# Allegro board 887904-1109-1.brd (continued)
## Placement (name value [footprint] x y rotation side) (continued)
NOREF#991  -  []  441.63 509.49 90 top
NOREF#992  -  []  100.65 170.14 90 top
NOREF#993  -  []  96.65 195.83 0 top
NOREF#994  -  []  388.78 537.62 90 top
NOREF#995  -  []  471.24 516.22 0 top
NOREF#996  -  []  100.65 175.29 0 top
NOREF#997  -  []  431.7 114.13 90 top
R11  49.9-1-S4  [R0402]  121.79 233.76 180 bottom
R12  49.9-1-S4  [R0402]  119.59 233.76 180 bottom
R13  49.9-1-S4  [R0402]  117.39 233.76 180 bottom
R14  49.9-1-S4  [R0402]  115.19 233.76 180 bottom
R15  49.9-1-S4  [R0402]  112.98 233.76 180 bottom
R16  49.9-1-S4  [R0402]  110.78 233.76 180 bottom
R17  49.9-1-S4  [R0402]  108.58 233.76 180 bottom
R18  49.9-1-S4  [R0402]  106.37 233.76 180 bottom
R19  49.9-1-S4  [R0402]  104.17 233.76 180 bottom
R20  49.9-1-S4  [R0402]  101.97 233.76 180 bottom
R21  49.9-1-S4  [R0402]  99.76 233.76 180 bottom
R22  49.9-1-S4  [R0402]  97.56 233.76 180 bottom
R23  49.9-1-S4  [R0402]  95.36 233.76 180 bottom
R24  49.9-1-S4  [R0402]  93.15 233.76 180 bottom
R25  49.9-1-S4  [R0402]  90.95 233.76 180 bottom
R26  49.9-1-S4  [R0402]  88.75 233.76 180 bottom
R51  NC/1M-1-S4  [R0402]  103.37 200.03 180 bottom
R52  NC/1M-1-S4  [R0402]  100.83 200.03 180 bottom
R53  NC/100K-1-S4  [R0402]  98.29 200.03 180 bottom
R54  NC/100K-1-S4  [R0402]  95.75 200.03 180 bottom
R55  100K-1-S4  [R0402]  101.32 177.88 180 bottom
R69  NC/4.7K-1-S4  [R0402]  48.13 269.88 180 bottom
R70  NC/4.7K-1-S4  [R0402]  45.59 269.88 180 bottom
R71  NC/4.7K-1-S4  [R0402]  43.05 269.88 180 bottom
R72  4.7K-1-S4-WA  [R0402]  50.67 269.88 180 bottom
R73  NC/4.7K-1-S4  [R0402]  40.51 269.88 180 bottom
R74  NC/4.7K-1-S4  [R0402]  37.97 269.88 180 bottom
R147  1.1K-1-S4  [R0402]  51.73 245.19 180 bottom
R148  1.1K-1-S4  [R0402]  49.53 245.19 180 bottom
R161  0-5-S4  [R0402]  113.53 200.03 180 bottom
R162  0-5-S4  [R0402]  110.99 200.03 180 bottom
R163  4.7K-1-S4-WA  [R0402]  53.21 269.88 180 bottom
R184  50-0.1-S4-HF-VI  [R0402]  108.45 200.03 180 bottom
R185  50-0.1-S4-HF-VI  [R0402]  105.91 200.03 180 bottom
R200  0-5-S4  [R0402]  39.24 217.17 180 bottom
R201  0-5-S4  [R0402]  49.4 212.09 180 bottom
R202  0-5-S4  [R0402]  47.49 203.84 180 bottom
R203  0-5-S4  [R0402]  43.05 195.58 180 bottom
R204  0-5-S4  [R0402]  44.95 187.32 180 bottom
R205  0-5-S4  [R0402]  46.86 179.07 180 bottom
R206  0-5-S4  [R0402]  49.4 170.81 180 bottom
R207  0-5-S4  [R0402]  35.43 161.93 180 bottom
R208  0-5-S4  [R0402]  50.03 153.67 180 bottom
R209  0-5-S4  [R0402]  47.49 146.69 180 bottom
RB1  10K-1-S6  [R0603]  326.15 559.2 0 top
RB2  10K-1-S6  [R0603]  322.95 559.2 0 top
SB1  SHORT  [DEFAULT_SHORT_SMALL]  23.7 559.13 0 top
SB2  SHORT  [DEFAULT_SHORT_SMALL]  30.31 559.13 0 top
SB3  SHORT  [DEFAULT_SHORT_SMALL]  32.51 559.13 0 top
SB8  SHORT  [DEFAULT_SHORT_SMALL]  34.71 559.13 0 top
SB11  SHORT  [DEFAULT_SHORT_SMALL]  25.9 559.13 0 top
SB12  SHORT  [DEFAULT_SHORT_SMALL]  28.1 559.13 0 top
SCREW1  V93KMFHOLE  [PG_VG93K_F_FULLOUTLINE]  290.83 214.63 0 top
SH1  SHORT  [DEFAULT_SHORT_SMALL]  26.54 217.17 180 bottom
SH2  SHORT  [DEFAULT_SHORT_SMALL]  29.08 217.17 180 bottom
SH3  SHORT  [DEFAULT_SHORT_SMALL]  31.62 212.09 180 bottom
SH4  SHORT  [DEFAULT_SHORT_SMALL]  34.16 212.09 180 bottom
SH5  SHORT  [DEFAULT_SHORT_SMALL]  37.33 203.84 180 bottom
SH6  SHORT  [DEFAULT_SHORT_SMALL]  39.87 203.84 180 bottom
SH7  SHORT  [DEFAULT_SHORT_SMALL]  32.89 195.58 180 bottom
SH8  SHORT  [DEFAULT_SHORT_SMALL]  37.97 195.58 180 bottom
SH9  SHORT  [DEFAULT_SHORT_SMALL]  39.87 187.32 180 bottom
SH10  SHORT  [DEFAULT_SHORT_SMALL]  34.79 187.32 180 bottom
SH11  SHORT  [DEFAULT_SHORT_SMALL]  39.24 179.07 180 bottom
SH12  SHORT  [DEFAULT_SHORT_SMALL]  36.7 179.07 180 bottom
SH13  SHORT  [DEFAULT_SHORT_SMALL]  41.78 170.81 180 bottom
SH14  SHORT  [DEFAULT_SHORT_SMALL]  39.24 170.81 180 bottom
SH15  SHORT  [DEFAULT_SHORT_SMALL]  45.59 161.93 180 bottom
SH16  SHORT  [DEFAULT_SHORT_SMALL]  48.13 161.93 180 bottom
SH17  SHORT  [DEFAULT_SHORT_SMALL]  37.33 153.67 180 bottom
SH18  SHORT  [DEFAULT_SHORT_SMALL]  39.87 153.67 180 bottom
SH19  SHORT  [DEFAULT_SHORT_SMALL]  37.33 146.69 180 bottom
SH20  SHORT  [DEFAULT_SHORT_SMALL]  39.87 146.69 180 bottom
SH21  SHORT  [DEFAULT_SHORT_SMALL]  205.26 271.48 0 top
SH22  SHORT  [DEFAULT_SHORT_SMALL]  207.46 271.48 0 top
SH23  SHORT  [DEFAULT_SHORT_SMALL]  190.37 269.88 0 top
SH24  SHORT  [DEFAULT_SHORT_SMALL]  190.37 269.88 0 top
SH25  SHORT  [DEFAULT_SHORT_SMALL]  197.99 269.88 0 top
SH26  SHORT  [DEFAULT_SHORT_SMALL]  197.99 269.88 0 top
SITE1  CU/887904-WFBGA75-10X3.5X0.636  [SK_WFBGA75P_0P65MM_JG_887904]  230.7 214.63 270 top
SITE2  CU/887904-WFBGA75-10X3.5X0.636  [SK_WFBGA75P_0P65MM_JG_887904]  270.7 214.63 270 top
SITE3  CU/887904-WFBGA75-10X3.5X0.636  [SK_WFBGA75P_0P65MM_JG_887904]  310.7 214.63 270 top
SITE4  CU/887904-WFBGA75-10X3.5X0.636  [SK_WFBGA75P_0P65MM_JG_887904]  350.7 214.63 270 top
SKB1  SKB-HIMAX-2SITE-M5-140X140-HON  [SOCKETBASE_294X213_888003]  290.7 214.63 0 top
SW1  SW-SLIDE-1-D2.54-ECE  [SW_DIPX1_2P_H5MM]  116.71 175.26 180 bottom
TP_S1_V25  TP01  [TP_040_T]  205.61 269.24 0 top
TP_VDD09_CORE  TP01  [TP_040_T]  44.32 217.17 180 bottom
TP_VDD_EFUSE_POWER  TP01  [TP_040_T]  190.37 269.88 0 top
TP_VDD_EFUSE_POWER1  TP01  [TP_040_T]  197.99 269.88 0 top
TP_VDD_IOB_18_BOOST  TP01  [TP_040_T]  47.49 153.67 180 bottom
TP_VDD_IOB_18_POR  TP01  [TP_040_T]  31.62 147.32 180 bottom
TP_VDD_PLL_09  TP01  [TP_040_T]  37.97 161.93 180 bottom
TP_VDD_TX_09  TP01  [TP_040_T]  29.08 186.69 180 bottom
TP_VDD_TX_09_HDO  TP01  [TP_040_T]  30.35 203.84 180 bottom
TP_VDD_TXPST_09  TP01  [TP_040_T]  27.17 194.94 180 bottom
TP_VDDIO_18  TP01  [TP_040_T]  24 212.09 180 bottom
TP_VDDRX_09  TP01  [TP_040_T]  33.52 171.45 180 bottom
TP_VDDRX_AUX  TP01  [TP_040_T]  31.62 179.07 180 bottom
TPL1  TPL01  [TPL_040_014_TB]  615.92 559.38 0 top
TPL2  TPL01  [TPL_040_014_TB]  631.77 559.38 0 top
TPL3  TPL01  [TPL_040_014_TB]  156.78 265.43 90 top
TPL4  TPL01  [TPL_040_014_TB]  156.78 269.24 90 top
TPL5  TPL01  [TPL_040_014_TB]  156.78 273.05 90 top
TPL6  TPL01  [TPL_040_014_TB]  156.78 276.86 90 top
TPL7  TPL01  [TPL_040_014_TB]  156.78 280.67 90 top
TPL8  TPL01  [TPL_040_014_TB]  156.78 284.48 90 top
TPL9  TPL01  [TPL_040_014_TB]  156.78 288.29 90 top
TPL10  TPL01  [TPL_040_014_TB]  617.9 559.38 0 top
TPL11  TPL01  [TPL_040_014_TB]  619.88 559.38 0 top
TPL12  TPL01  [TPL_040_014_TB]  621.86 559.38 0 top
TPL13  TPL01  [TPL_040_014_TB]  623.85 559.38 0 top
TPL14  TPL01  [TPL_040_014_TB]  625.83 559.38 0 top
TPL15  TPL01  [TPL_040_014_TB]  627.81 559.38 0 top
TPL16  TPL01  [TPL_040_014_TB]  629.79 559.38 0 top
U5  SK-SO8-1.27-LOTES-150  [SK_SO8_150_1P27MM_LOTES]  25.02 262.29 180 bottom
UB1  AT24C04C-SSHM-SO8  [SO8_215X127MM]  511.27 524.59 0 top
UF1  MX25U4035FM1I-SOP8  [SOCKET_CODE]  35.43 269.88 180 bottom
UNK2C1  0.1U-16-X-S4-MU  [C0402]  312.64 559.05 0 top
UNK2C53  0.1U-16-X-S4-MU  [C0402]  310.43 559.05 0 top
UNK2C54  0.1U-16-X-S4-MU  [C0402]  308.23 559.05 0 top
UNK2C55  0.1U-16-X-S4-MU  [C0402]  306.03 559.05 0 top
UNK2C67  1U-10-X-S4-MU  [C0402]  266.37 559.05 0 top
UNK2C69  10U-25-X7R-SA  [C1206]  74.95 557.04 0 top
UNK2C70  10U-25-X7R-SA  [C1206]  70.35 557.04 0 top
UNK2C71  1U-10-X-S4-MU  [C0402]  264.17 559.05 0 top
UNK2C73  1U-10-X-S4-MU  [C0402]  261.96 559.05 0 top
UNK2C75  1U-10-X-S4-MU  [C0402]  259.76 559.05 0 top
UNK2C77  1U-10-X-S4-MU  [C0402]  257.56 559.05 0 top
UNK2C79  1U-10-X-S4-MU  [C0402]  255.35 559.05 0 top
UNK2C81  1U-10-X-S4-MU  [C0402]  253.15 559.05 0 top
UNK2C83  1U-10-X-S4-MU  [C0402]  250.95 559.05 0 top
UNK2C85  1U-10-X-S4-MU  [C0402]  248.74 559.05 0 top
UNK2C87  1U-10-X-S4-MU  [C0402]  246.54 559.05 0 top
UNK2C89  10U-25-X7R-SA  [C1206]  65.75 557.04 0 top
UNK2C90  10U-25-X7R-SA  [C1206]  61.14 557.04 0 top
UNK2C91  10U-25-X7R-SA  [C1206]  56.54 557.04 0 top
UNK2C92  10U-25-X7R-SA  [C1206]  51.94 557.04 0 top
UNK2C93  10U-25-X7R-SA  [C1206]  47.34 557.04 0 top
UNK2C94  10U-25-X7R-SA  [C1206]  627.61 538.78 0 top
UNK2C95  10U-25-X7R-SA  [C1206]  623.01 538.78 0 top
UNK2C96  10U-25-X7R-SA  [C1206]  618.4 538.78 0 top
UNK2CA1  NC/2.2U-10-X-S4-MU  [C0402]  437.28 538.08 0 top
UNK2CA2  NC/2.2U-10-X-S4-MU  [C0402]  432.87 538.08 0 top
UNK2CA3  NC/2.2U-10-X-S4-MU  [C0402]  430.67 538.08 0 top
UNK2CA4  NC/2.2U-10-X-S4-MU  [C0402]  123.42 559.05 0 top
UNK2CA5  NC/2.2U-10-X-S4-MU  [C0402]  121.22 559.05 0 top
UNK2CA6  NC/2.2U-10-X-S4-MU  [C0402]  119.01 559.05 0 top
UNK2CA7  NC/2.2U-10-X-S4-MU  [C0402]  137.04 556.34 0 top
UNK2CA8  NC/2.2U-10-X-S4-MU  [C0402]  133.44 556.34 0 top
UNK2CA9  NC/2.2U-10-X-S4-MU  [C0402]  131.23 556.34 0 top
UNK2CA10  NC/2.2U-10-X-S4-MU  [C0402]  435.08 538.08 0 top
UNK2CC1  0.47U-10-X6S-S2-TY  [C0201]  1.07 556.2 0 top
UNK2CC2  0.47U-10-X6S-S2-TY  [C0201]  630.61 537.94 0 top
UNK2CC3  0.47U-10-X6S-S2-TY  [C0201]  443.69 537.94 0 top
UNK2CC4  0.47U-10-X6S-S2-TY  [C0201]  354.5 537.94 0 top
UNK2CC5  0.47U-10-X6S-S2-TY  [C0201]  303.99 537.94 0 top
UNK2CC6  0.47U-10-X6S-S2-TY  [C0201]  289.96 537.94 0 top
UNK2CC7  0.47U-10-X6S-S2-TY  [C0201]  288.56 537.94 0 top
UNK2CC8  0.47U-10-X6S-S2-TY  [C0201]  284.35 537.94 0 top
UNK2CC9  0.47U-10-X6S-S2-TY  [C0201]  281.54 537.94 0 top
UNK2CC10  0.47U-10-X6S-S2-TY  [C0201]  -0.33 556.2 0 top
UNK2CC11  0.47U-10-X6S-S2-TY  [C0201]  -1.74 556.2 0 top
UNK2CC12  0.47U-10-X6S-S2-TY  [C0201]  -3.14 556.2 0 top
UNK2CC13  0.47U-10-X6S-S2-TY  [C0201]  634.82 537.94 0 top
UNK2CC14  0.47U-10-X6S-S2-TY  [C0201]  633.42 537.94 0 top
UNK2CC15  0.47U-10-X6S-S2-TY  [C0201]  632.01 537.94 0 top
UNK2CD1  0.1U-10-X7R-S2-MU  [C0201]  346.08 537.94 0 top
UNK2CD2  0.1U-10-X7R-S2-MU  [C0201]  398 537.94 0 top
UNK2CD3  0.1U-10-X7R-S2-MU  [C0201]  357.31 537.94 0 top
UNK2CD4  0.1U-10-X7R-S2-MU  [C0201]  358.71 537.94 0 top
UNK2CD5  0.1U-10-X7R-S2-MU  [C0201]  360.12 537.94 0 top
UNK2CD6  0.1U-10-X7R-S2-MU  [C0201]  361.52 537.94 0 top
UNK2CD7  0.1U-10-X7R-S2-MU  [C0201]  362.92 537.94 0 top
UNK2CD8  0.1U-10-X7R-S2-MU  [C0201]  364.32 537.94 0 top
UNK2CD9  0.1U-10-X7R-S2-MU  [C0201]  365.73 537.94 0 top
UNK2CD10  0.1U-10-X7R-S2-MU  [C0201]  347.49 537.94 0 top
UNK2CD11  0.1U-10-X7R-S2-MU  [C0201]  399.4 537.94 0 top
UNK2CD12  0.1U-10-X7R-S2-MU  [C0201]  350.29 537.94 0 top
UNK2CD13  0.1U-10-X7R-S2-MU  [C0201]  351.7 537.94 0 top
UNK2CD14  0.1U-10-X7R-S2-MU  [C0201]  353.1 537.94 0 top
UNK2CD15  0.1U-10-X7R-S2-MU  [C0201]  424.66 537.94 0 top
UNK2GND1  TP01  [TP_040_T]  20.92 582.23 0 top
UNK2K9  UA2-5NJ-A-V3  [RL_NECUA2_5V_V3]  408.95 524.93 0 top
UNK2K10  UA2-5NJ-A-V3  [RL_NECUA2_5V_V3]  475.57 524.93 0 top
UNK2K14  UA2-5NJ-A-V3  [RL_NECUA2_5V_V3]  464.47 524.93 0 top
UNK2K15  UA2-5NJ-A-V3  [RL_NECUA2_5V_V3]  453.36 524.93 0 top
UNK2K28  UA2-5NJ-A-V3  [RL_NECUA2_5V_V3]  442.26 524.93 0 top
UNK2K48  UA2-5NJ-A-V3  [RL_NECUA2_5V_V3]  431.16 524.93 0 top
UNK2K50  UA2-5NJ-A-V3  [RL_NECUA2_5V_V3]  420.06 524.93 0 top
UNK2K54  G6K-2F-RF-T-5V-SPECIAL  [RL_G6K2FRT_8P_5V_GR]  472.89 512.22 0 top
UNK2K55  EC2-5NJ-A  [RL_NECEC2_10P_5V]  512.55 510.07 0 top
UNK2K56  EC2-5NJ-A  [RL_NECEC2_10P_5V]  173.54 525.68 0 top
UNK2K57  EC2-5NJ-A  [RL_NECEC2_10P_5V]  158.33 525.68 0 top
UNK2K58  EC2-5NJ-A  [RL_NECEC2_10P_5V]  143.13 525.68 0 top
UNK2K59  EC2-5NJ-A  [RL_NECEC2_10P_5V]  127.93 525.68 0 top
UNK2K60  G6K-2F-RF-T-5V-SPECIAL  [RL_G6K2FRT_8P_5V_GR]  447.28 512.22 0 top
UNK2K61  G6K-2F-RF-T-5V-SPECIAL  [RL_G6K2FRT_8P_5V_GR]  370.46 512.22 0 top
UNK2K62  G6K-2F-RF-T-5V-SPECIAL  [RL_G6K2FRT_8P_5V_GR]  306.45 512.22 0 top
UNK2R11  49.9-1-S4  [R0402]  140.65 556.34 0 top
UNK2R12  49.9-1-S4  [R0402]  142.85 556.34 0 top
UNK2R13  49.9-1-S4  [R0402]  223.57 556.34 0 top
UNK2R14  49.9-1-S4  [R0402]  146.46 556.34 0 top
UNK2R15  49.9-1-S4  [R0402]  148.66 556.34 0 top
UNK2R16  49.9-1-S4  [R0402]  150.86 556.34 0 top
UNK2R17  49.9-1-S4  [R0402]  153.07 556.34 0 top
UNK2R18  49.9-1-S4  [R0402]  155.27 556.34 0 top
UNK2R19  49.9-1-S4  [R0402]  157.47 556.34 0 top
UNK2R20  49.9-1-S4  [R0402]  159.68 556.34 0 top
UNK2R21  49.9-1-S4  [R0402]  161.88 556.34 0 top
UNK2R22  49.9-1-S4  [R0402]  164.08 556.34 0 top
UNK2R23  49.9-1-S4  [R0402]  166.29 556.34 0 top
UNK2R24  49.9-1-S4  [R0402]  168.49 556.34 0 top
UNK2R25  49.9-1-S4  [R0402]  170.69 556.34 0 top
UNK2R26  49.9-1-S4  [R0402]  172.9 556.34 0 top
UNK2R51  NC/1M-1-S4  [R0402]  439.48 556.34 0 top
UNK2R52  NC/1M-1-S4  [R0402]  441.69 556.34 0 top
UNK2R53  NC/100K-1-S4  [R0402]  457.11 556.34 0 top
UNK2R54  NC/100K-1-S4  [R0402]  459.31 556.34 0 top
UNK2R55  100K-1-S4  [R0402]  474.73 556.34 0 top
UNK2R69  NC/4.7K-1-S4  [R0402]  483.55 556.34 0 top
UNK2R70  NC/4.7K-1-S4  [R0402]  485.75 556.34 0 top
UNK2R71  NC/4.7K-1-S4  [R0402]  487.95 556.34 0 top
UNK2R72  4.7K-1-S4-WA  [R0402]  406.44 556.34 0 top
UNK2R73  NC/4.7K-1-S4  [R0402]  490.16 556.34 0 top
UNK2R74  NC/4.7K-1-S4  [R0402]  492.36 556.34 0 top
UNK2R147  1.1K-1-S4  [R0402]  280.85 556.34 0 top
UNK2R148  1.1K-1-S4  [R0402]  283.06 556.34 0 top
UNK2R161  0-5-S4  [R0402]  298.48 556.34 0 top
UNK2R162  0-5-S4  [R0402]  300.68 556.34 0 top
UNK2R163  4.7K-1-S4-WA  [R0402]  404.23 556.34 0 top
UNK2R184  50-0.1-S4-HF-VI  [R0402]  421.86 556.34 0 top
UNK2R185  50-0.1-S4-HF-VI  [R0402]  424.06 556.34 0 top
UNK2R200  0-5-S4  [R0402]  302.89 556.34 0 top
UNK2R201  0-5-S4  [R0402]  305.09 556.34 0 top
UNK2R202  0-5-S4  [R0402]  307.29 556.34 0 top
UNK2R203  0-5-S4  [R0402]  309.49 556.34 0 top
UNK2R204  0-5-S4  [R0402]  311.7 556.34 0 top
UNK2R205  0-5-S4  [R0402]  313.9 556.34 0 top
UNK2R206  0-5-S4  [R0402]  316.1 556.34 0 top
UNK2R207  0-5-S4  [R0402]  318.31 556.34 0 top
UNK2R208  0-5-S4  [R0402]  320.51 556.34 0 top
UNK2R209  0-5-S4  [R0402]  322.71 556.34 0 top
UNK2SH1  SHORT  [DEFAULT_SHORT_SMALL]  527.61 556.43 0 top
UNK2SH2  SHORT  [DEFAULT_SHORT_SMALL]  551.85 556.43 0 top
UNK2SH3  SHORT  [DEFAULT_SHORT_SMALL]  556.25 556.43 0 top
UNK2SH4  SHORT  [DEFAULT_SHORT_SMALL]  558.46 556.43 0 top
UNK2SH5  SHORT  [DEFAULT_SHORT_SMALL]  560.66 556.43 0 top
UNK2SH6  SHORT  [DEFAULT_SHORT_SMALL]  562.86 556.43 0 top
UNK2SH7  SHORT  [DEFAULT_SHORT_SMALL]  565.07 556.43 0 top
UNK2SH8  SHORT  [DEFAULT_SHORT_SMALL]  567.27 556.43 0 top
UNK2SH9  SHORT  [DEFAULT_SHORT_SMALL]  569.47 556.43 0 top
UNK2SH10  SHORT  [DEFAULT_SHORT_SMALL]  529.81 556.43 0 top
UNK2SH11  SHORT  [DEFAULT_SHORT_SMALL]  532.02 556.43 0 top
UNK2SH12  SHORT  [DEFAULT_SHORT_SMALL]  534.22 556.43 0 top
UNK2SH13  SHORT  [DEFAULT_SHORT_SMALL]  536.42 556.43 0 top
UNK2SH14  SHORT  [DEFAULT_SHORT_SMALL]  538.63 556.43 0 top
UNK2SH15  SHORT  [DEFAULT_SHORT_SMALL]  540.83 556.43 0 top
UNK2SH16  SHORT  [DEFAULT_SHORT_SMALL]  543.03 556.43 0 top
UNK2SH17  SHORT  [DEFAULT_SHORT_SMALL]  545.24 556.43 0 top
UNK2SH18  SHORT  [DEFAULT_SHORT_SMALL]  547.44 556.43 0 top
UNK2SH19  SHORT  [DEFAULT_SHORT_SMALL]  549.64 556.43 0 top
UNK2SH20  SHORT  [DEFAULT_SHORT_SMALL]  554.05 556.43 0 top
UNK2SW1  SW-SLIDE-1-D2.54-ECE  [SW_DIPX1_2P_H5MM]  96.2 563.75 0 top
UNK2TP_VDD09_CORE  TP01  [TP_040_T]  18.94 582.23 0 top
UNK2TP_VDD_IOB_18_BOOST  TP01  [TP_040_T]  11.02 582.23 0 top
UNK2TP_VDD_IOB_18_POR  TP01  [TP_040_T]  613.94 559.38 0 top
UNK2TP_VDD_PLL_09  TP01  [TP_040_T]  611.96 559.38 0 top
UNK2TP_VDD_TX_09  TP01  [TP_040_T]  608 559.38 0 top
UNK2TP_VDD_TX_09_HDO  TP01  [TP_040_T]  606.01 559.38 0 top
UNK2TP_VDD_TXPST_09  TP01  [TP_040_T]  609.98 559.38 0 top
UNK2TP_VDDIO_18  TP01  [TP_040_T]  16.96 582.23 0 top
UNK2TP_VDDRX_09  TP01  [TP_040_T]  14.98 582.23 0 top
UNK2TP_VDDRX_AUX  TP01  [TP_040_T]  13 582.23 0 top
UNK2U5  SK-SO8-1.27-LOTES-150  [SK_SO8_150_1P27MM_LOTES]  547.66 514.02 0 top
UNK2UF1  MX25U4035FM1I-SOP8  [SOCKET_CODE]  334.66 558.9 0 top
UNK3C1  0.1U-16-X-S4-MU  [C0402]  303.82 559.05 0 top
UNK3C53  0.1U-16-X-S4-MU  [C0402]  301.62 559.05 0 top
UNK3C54  0.1U-16-X-S4-MU  [C0402]  299.42 559.05 0 top
UNK3C55  0.1U-16-X-S4-MU  [C0402]  297.21 559.05 0 top
UNK3C67  1U-10-X-S4-MU  [C0402]  244.34 559.05 0 top
UNK3C69  10U-25-X7R-SA  [C1206]  613.8 538.78 0 top
UNK3C70  10U-25-X7R-SA  [C1206]  609.2 538.78 0 top
UNK3C71  1U-10-X-S4-MU  [C0402]  242.13 559.05 0 top
UNK3C73  1U-10-X-S4-MU  [C0402]  239.93 559.05 0 top
UNK3C75  1U-10-X-S4-MU  [C0402]  237.73 559.05 0 top
UNK3C77  1U-10-X-S4-MU  [C0402]  235.52 559.05 0 top
UNK3C79  1U-10-X-S4-MU  [C0402]  233.32 559.05 0 top
UNK3C81  1U-10-X-S4-MU  [C0402]  231.12 559.05 0 top
UNK3C83  1U-10-X-S4-MU  [C0402]  228.91 559.05 0 top
UNK3C85  1U-10-X-S4-MU  [C0402]  226.71 559.05 0 top
UNK3C87  1U-10-X-S4-MU  [C0402]  224.51 559.05 0 top
UNK3C89  10U-25-X7R-SA  [C1206]  604.59 538.78 0 top
UNK3C90  10U-25-X7R-SA  [C1206]  599.99 538.78 0 top
UNK3C91  10U-25-X7R-SA  [C1206]  595.39 538.78 0 top
UNK3C92  10U-25-X7R-SA  [C1206]  590.78 538.78 0 top
UNK3C93  10U-25-X7R-SA  [C1206]  586.18 538.78 0 top
UNK3C94  10U-25-X7R-SA  [C1206]  581.58 538.78 0 top
UNK3C95  10U-25-X7R-SA  [C1206]  576.98 538.78 0 top
UNK3C96  10U-25-X7R-SA  [C1206]  572.37 538.78 0 top
UNK3CA1  NC/2.2U-10-X-S4-MU  [C0402]  129.03 556.34 0 top
UNK3CA2  NC/2.2U-10-X-S4-MU  [C0402]  124.62 556.34 0 top
UNK3CA3  NC/2.2U-10-X-S4-MU  [C0402]  122.42 556.34 0 top
UNK3CA4  NC/2.2U-10-X-S4-MU  [C0402]  120.22 556.34 0 top
UNK3CA5  NC/2.2U-10-X-S4-MU  [C0402]  118.01 556.34 0 top
UNK3CA6  NC/2.2U-10-X-S4-MU  [C0402]  115.81 556.34 0 top
UNK3CA7  NC/2.2U-10-X-S4-MU  [C0402]  113.61 556.34 0 top
UNK3CA8  NC/2.2U-10-X-S4-MU  [C0402]  111.4 556.34 0 top
UNK3CA9  NC/2.2U-10-X-S4-MU  [C0402]  109.2 556.34 0 top
UNK3CA10  NC/2.2U-10-X-S4-MU  [C0402]  126.83 556.34 0 top
UNK3CC1  0.47U-10-X6S-S2-TY  [C0201]  282.95 537.94 0 top
UNK3CC2  0.47U-10-X6S-S2-TY  [C0201]  305.39 537.94 0 top
UNK3CC3  0.47U-10-X6S-S2-TY  [C0201]  311.01 537.94 0 top
UNK3CC4  0.47U-10-X6S-S2-TY  [C0201]  295.57 537.94 0 top
UNK3CC5  0.47U-10-X6S-S2-TY  [C0201]  296.98 537.94 0 top
UNK3CC6  0.47U-10-X6S-S2-TY  [C0201]  298.38 537.94 0 top
UNK3CC7  0.47U-10-X6S-S2-TY  [C0201]  299.78 537.94 0 top
UNK3CC8  0.47U-10-X6S-S2-TY  [C0201]  315.22 537.94 0 top
UNK3CC9  0.47U-10-X6S-S2-TY  [C0201]  302.59 537.94 0 top
UNK3CC10  0.47U-10-X6S-S2-TY  [C0201]  292.77 537.94 0 top
UNK3CC11  0.47U-10-X6S-S2-TY  [C0201]  285.75 537.94 0 top
UNK3CC12  0.47U-10-X6S-S2-TY  [C0201]  287.15 537.94 0 top
UNK3CC13  0.47U-10-X6S-S2-TY  [C0201]  294.17 537.94 0 top
UNK3CC14  0.47U-10-X6S-S2-TY  [C0201]  301.19 537.94 0 top
UNK3CC15  0.47U-10-X6S-S2-TY  [C0201]  291.36 537.94 0 top
UNK3CD1  0.1U-10-X7R-S2-MU  [C0201]  367.13 537.94 0 top
UNK3CD2  0.1U-10-X7R-S2-MU  [C0201]  376.95 537.94 0 top
UNK3CD3  0.1U-10-X7R-S2-MU  [C0201]  378.36 537.94 0 top
UNK3CD4  0.1U-10-X7R-S2-MU  [C0201]  379.76 537.94 0 top
UNK3CD5  0.1U-10-X7R-S2-MU  [C0201]  381.16 537.94 0 top
UNK3CD6  0.1U-10-X7R-S2-MU  [C0201]  382.57 537.94 0 top
UNK3CD7  0.1U-10-X7R-S2-MU  [C0201]  445.09 537.94 0 top
UNK3CD8  0.1U-10-X7R-S2-MU  [C0201]  385.37 537.94 0 top
UNK3CD9  0.1U-10-X7R-S2-MU  [C0201]  386.77 537.94 0 top
UNK3CD10  0.1U-10-X7R-S2-MU  [C0201]  368.53 537.94 0 top
UNK3CD11  0.1U-10-X7R-S2-MU  [C0201]  369.94 537.94 0 top
UNK3CD12  0.1U-10-X7R-S2-MU  [C0201]  371.34 537.94 0 top
UNK3CD13  0.1U-10-X7R-S2-MU  [C0201]  372.74 537.94 0 top
UNK3CD14  0.1U-10-X7R-S2-MU  [C0201]  374.15 537.94 0 top
UNK3CD15  0.1U-10-X7R-S2-MU  [C0201]  375.55 537.94 0 top
UNK3GND1  TP01  [TP_040_T]  604.03 559.38 0 top
UNK3K9  UA2-5NJ-A-V3  [RL_NECUA2_5V_V3]  331.23 524.93 0 top
UNK3K10  UA2-5NJ-A-V3  [RL_NECUA2_5V_V3]  397.85 524.93 0 top
UNK3K14  UA2-5NJ-A-V3  [RL_NECUA2_5V_V3]  386.75 524.93 0 top
UNK3K15  UA2-5NJ-A-V3  [RL_NECUA2_5V_V3]  375.64 524.93 0 top
UNK3K28  UA2-5NJ-A-V3  [RL_NECUA2_5V_V3]  364.54 524.93 0 top
UNK3K48  UA2-5NJ-A-V3  [RL_NECUA2_5V_V3]  353.44 524.93 0 top
UNK3K50  UA2-5NJ-A-V3  [RL_NECUA2_5V_V3]  342.33 524.93 0 top
UNK3K54  G6K-2F-RF-T-5V-SPECIAL  [RL_G6K2FRT_8P_5V_GR]  319.25 512.22 0 top
UNK3K55  EC2-5NJ-A  [RL_NECEC2_10P_5V]  112.72 525.68 0 top
UNK3K56  EC2-5NJ-A  [RL_NECEC2_10P_5V]  97.52 525.68 0 top
UNK3K57  EC2-5NJ-A  [RL_NECEC2_10P_5V]  82.32 525.68 0 top
UNK3K58  EC2-5NJ-A  [RL_NECEC2_10P_5V]  67.11 525.68 0 top
UNK3K59  EC2-5NJ-A  [RL_NECEC2_10P_5V]  51.91 525.68 0 top
UNK3K60  G6K-2F-RF-T-5V-SPECIAL  [RL_G6K2FRT_8P_5V_GR]  332.05 512.22 0 top
UNK3K61  G6K-2F-RF-T-5V-SPECIAL  [RL_G6K2FRT_8P_5V_GR]  357.66 512.22 0 top
UNK3K62  G6K-2F-RF-T-5V-SPECIAL  [RL_G6K2FRT_8P_5V_GR]  344.85 512.22 0 top
UNK3R11  49.9-1-S4  [R0402]  175.1 556.34 0 top
UNK3R12  49.9-1-S4  [R0402]  177.3 556.34 0 top
UNK3R13  49.9-1-S4  [R0402]  179.51 556.34 0 top
UNK3R14  49.9-1-S4  [R0402]  181.71 556.34 0 top
UNK3R15  49.9-1-S4  [R0402]  183.91 556.34 0 top
UNK3R16  49.9-1-S4  [R0402]  186.12 556.34 0 top
UNK3R17  49.9-1-S4  [R0402]  188.32 556.34 0 top
UNK3R18  49.9-1-S4  [R0402]  190.52 556.34 0 top
UNK3R19  49.9-1-S4  [R0402]  192.73 556.34 0 top
UNK3R20  49.9-1-S4  [R0402]  194.93 556.34 0 top
UNK3R21  49.9-1-S4  [R0402]  197.13 556.34 0 top
UNK3R22  49.9-1-S4  [R0402]  314.84 559.05 0 top
UNK3R23  49.9-1-S4  [R0402]  317.04 559.05 0 top
UNK3R24  49.9-1-S4  [R0402]  203.74 556.34 0 top
UNK3R25  49.9-1-S4  [R0402]  205.94 556.34 0 top
UNK3R26  49.9-1-S4  [R0402]  208.15 556.34 0 top
UNK3R51  NC/1M-1-S4  [R0402]  443.89 556.34 0 top
UNK3R52  NC/1M-1-S4  [R0402]  446.09 556.34 0 top
UNK3R53  NC/100K-1-S4  [R0402]  461.52 556.34 0 top
UNK3R54  NC/100K-1-S4  [R0402]  463.72 556.34 0 top
UNK3R55  100K-1-S4  [R0402]  476.94 556.34 0 top
UNK3R69  NC/4.7K-1-S4  [R0402]  494.56 556.34 0 top
UNK3R70  NC/4.7K-1-S4  [R0402]  496.77 556.34 0 top
UNK3R71  NC/4.7K-1-S4  [R0402]  498.97 556.34 0 top
UNK3R72  4.7K-1-S4-WA  [R0402]  410.84 556.34 0 top
UNK3R73  NC/4.7K-1-S4  [R0402]  501.17 556.34 0 top
UNK3R74  NC/4.7K-1-S4  [R0402]  503.38 556.34 0 top
UNK3R147  1.1K-1-S4  [R0402]  285.26 556.34 0 top
UNK3R148  1.1K-1-S4  [R0402]  287.46 556.34 0 top
UNK3R161  0-5-S4  [R0402]  324.92 556.34 0 top
UNK3R162  0-5-S4  [R0402]  327.12 556.34 0 top
UNK3R163  4.7K-1-S4-WA  [R0402]  408.64 556.34 0 top
UNK3R184  50-0.1-S4-HF-VI  [R0402]  426.26 556.34 0 top
UNK3R185  50-0.1-S4-HF-VI  [R0402]  428.47 556.34 0 top
UNK3R200  0-5-S4  [R0402]  329.32 556.34 0 top
UNK3R201  0-5-S4  [R0402]  331.53 556.34 0 top
UNK3R202  0-5-S4  [R0402]  333.73 556.34 0 top
UNK3R203  0-5-S4  [R0402]  335.93 556.34 0 top
UNK3R204  0-5-S4  [R0402]  338.14 556.34 0 top
UNK3R205  0-5-S4  [R0402]  340.34 556.34 0 top
UNK3R206  0-5-S4  [R0402]  342.54 556.34 0 top
UNK3R207  0-5-S4  [R0402]  344.75 556.34 0 top
UNK3R208  0-5-S4  [R0402]  346.95 556.34 0 top
UNK3R209  0-5-S4  [R0402]  349.15 556.34 0 top
UNK3SH1  SHORT  [DEFAULT_SHORT_SMALL]  571.68 556.43 0 top
UNK3SH2  SHORT  [DEFAULT_SHORT_SMALL]  595.91 556.43 0 top
UNK3SH3  SHORT  [DEFAULT_SHORT_SMALL]  600.32 556.43 0 top
UNK3SH4  SHORT  [DEFAULT_SHORT_SMALL]  602.52 556.43 0 top
UNK3SH5  SHORT  [DEFAULT_SHORT_SMALL]  604.72 556.43 0 top
UNK3SH6  SHORT  [DEFAULT_SHORT_SMALL]  606.93 556.43 0 top
UNK3SH7  SHORT  [DEFAULT_SHORT_SMALL]  609.13 556.43 0 top
UNK3SH8  SHORT  [DEFAULT_SHORT_SMALL]  611.33 556.43 0 top
UNK3SH9  SHORT  [DEFAULT_SHORT_SMALL]  613.54 556.43 0 top
UNK3SH10  SHORT  [DEFAULT_SHORT_SMALL]  573.88 556.43 0 top
UNK3SH11  SHORT  [DEFAULT_SHORT_SMALL]  576.08 556.43 0 top
UNK3SH12  SHORT  [DEFAULT_SHORT_SMALL]  578.28 556.43 0 top
UNK3SH13  SHORT  [DEFAULT_SHORT_SMALL]  580.49 556.43 0 top
UNK3SH14  SHORT  [DEFAULT_SHORT_SMALL]  582.69 556.43 0 top
UNK3SH15  SHORT  [DEFAULT_SHORT_SMALL]  584.89 556.43 0 top
UNK3SH16  SHORT  [DEFAULT_SHORT_SMALL]  587.1 556.43 0 top
UNK3SH17  SHORT  [DEFAULT_SHORT_SMALL]  589.3 556.43 0 top
UNK3SH18  SHORT  [DEFAULT_SHORT_SMALL]  591.5 556.43 0 top
UNK3SH19  SHORT  [DEFAULT_SHORT_SMALL]  593.71 556.43 0 top
UNK3SH20  SHORT  [DEFAULT_SHORT_SMALL]  598.11 556.43 0 top
UNK3SW1  SW-SLIDE-1-D2.54-ECE  [SW_DIPX1_2P_H5MM]  102.4 563.75 0 top
UNK3TP_VDD09_CORE  TP01  [TP_040_T]  396.63 559.38 0 top
UNK3TP_VDD_IOB_18_BOOST  TP01  [TP_040_T]  388.7 559.38 0 top
UNK3TP_VDD_IOB_18_POR  TP01  [TP_040_T]  386.72 559.38 0 top
UNK3TP_VDD_PLL_09  TP01  [TP_040_T]  384.74 559.38 0 top
UNK3TP_VDD_TX_09  TP01  [TP_040_T]  462.01 559.38 0 top
UNK3TP_VDD_TX_09_HDO  TP01  [TP_040_T]  380.17 559.38 0 top
UNK3TP_VDD_TXPST_09  TP01  [TP_040_T]  597.43 559.38 0 top
UNK3TP_VDDIO_18  TP01  [TP_040_T]  394.65 559.38 0 top
UNK3TP_VDDRX_09  TP01  [TP_040_T]  392.67 559.38 0 top
UNK3TP_VDDRX_AUX  TP01  [TP_040_T]  390.69 559.38 0 top
UNK3U5  SK-SO8-1.27-LOTES-150  [SK_SO8_150_1P27MM_LOTES]  536.65 514.02 0 top
UNK3UF1  MX25U4035FM1I-SOP8  [SOCKET_CODE]  351.12 558.9 0 top
UNK4C1  0.1U-16-X-S4-MU  [C0402]  295.01 559.05 0 top
UNK4C53  0.1U-16-X-S4-MU  [C0402]  292.81 559.05 0 top
UNK4C54  0.1U-16-X-S4-MU  [C0402]  290.6 559.05 0 top
UNK4C55  0.1U-16-X-S4-MU  [C0402]  288.4 559.05 0 top
UNK4C67  1U-10-X-S4-MU  [C0402]  222.3 559.05 0 top
UNK4C69  10U-25-X7R-SA  [C1206]  567.77 538.78 0 top
UNK4C70  10U-25-X7R-SA  [C1206]  563.17 538.78 0 top
UNK4C71  1U-10-X-S4-MU  [C0402]  220.1 559.05 0 top
UNK4C73  1U-10-X-S4-MU  [C0402]  217.9 559.05 0 top
UNK4C75  1U-10-X-S4-MU  [C0402]  215.7 559.05 0 top
UNK4C77  1U-10-X-S4-MU  [C0402]  134.43 559.05 0 top
UNK4C79  1U-10-X-S4-MU  [C0402]  132.23 559.05 0 top
UNK4C81  1U-10-X-S4-MU  [C0402]  130.03 559.05 0 top
UNK4C83  1U-10-X-S4-MU  [C0402]  127.83 559.05 0 top
UNK4C85  1U-10-X-S4-MU  [C0402]  201.54 556.34 0 top
UNK4C87  1U-10-X-S4-MU  [C0402]  199.33 556.34 0 top
UNK4C89  10U-25-X7R-SA  [C1206]  558.56 538.78 0 top
UNK4C90  10U-25-X7R-SA  [C1206]  553.96 538.78 0 top
UNK4C91  10U-25-X7R-SA  [C1206]  549.36 538.78 0 top
UNK4C92  10U-25-X7R-SA  [C1206]  544.76 538.78 0 top
UNK4C93  10U-25-X7R-SA  [C1206]  540.15 538.78 0 top
UNK4C94  10U-25-X7R-SA  [C1206]  535.55 538.78 0 top
UNK4C95  10U-25-X7R-SA  [C1206]  530.95 538.78 0 top
UNK4C96  10U-25-X7R-SA  [C1206]  526.34 538.78 0 top
UNK4CA1  NC/2.2U-10-X-S4-MU  [C0402]  107 556.34 0 top
UNK4CA2  NC/2.2U-10-X-S4-MU  [C0402]  102.59 556.34 0 top
UNK4CA3  NC/2.2U-10-X-S4-MU  [C0402]  100.39 556.34 0 top
UNK4CA4  NC/2.2U-10-X-S4-MU  [C0402]  42.53 556.34 0 top
UNK4CA5  NC/2.2U-10-X-S4-MU  [C0402]  40.33 556.34 0 top
UNK4CA6  NC/2.2U-10-X-S4-MU  [C0402]  38.12 556.34 0 top
UNK4CA7  NC/2.2U-10-X-S4-MU  [C0402]  35.92 556.34 0 top
UNK4CA8  NC/2.2U-10-X-S4-MU  [C0402]  33.72 556.34 0 top
UNK4CA9  NC/2.2U-10-X-S4-MU  [C0402]  31.51 556.34 0 top
UNK4CA10  NC/2.2U-10-X-S4-MU  [C0402]  104.79 556.34 0 top
UNK4CC1  0.47U-10-X6S-S2-TY  [C0201]  327.84 537.94 0 top
UNK4CC2  0.47U-10-X6S-S2-TY  [C0201]  348.89 537.94 0 top
UNK4CC3  0.47U-10-X6S-S2-TY  [C0201]  334.86 537.94 0 top
UNK4CC4  0.47U-10-X6S-S2-TY  [C0201]  316.62 537.94 0 top
UNK4CC5  0.47U-10-X6S-S2-TY  [C0201]  318.02 537.94 0 top
UNK4CC6  0.47U-10-X6S-S2-TY  [C0201]  319.43 537.94 0 top
UNK4CC7  0.47U-10-X6S-S2-TY  [C0201]  320.83 537.94 0 top
UNK4CC8  0.47U-10-X6S-S2-TY  [C0201]  322.23 537.94 0 top
UNK4CC9  0.47U-10-X6S-S2-TY  [C0201]  323.64 537.94 0 top
UNK4CC10  0.47U-10-X6S-S2-TY  [C0201]  313.81 537.94 0 top
UNK4CC11  0.47U-10-X6S-S2-TY  [C0201]  306.8 537.94 0 top
UNK4CC12  0.47U-10-X6S-S2-TY  [C0201]  308.2 537.94 0 top
UNK4CC13  0.47U-10-X6S-S2-TY  [C0201]  309.6 537.94 0 top
UNK4CC14  0.47U-10-X6S-S2-TY  [C0201]  336.26 537.94 0 top
UNK4CC15  0.47U-10-X6S-S2-TY  [C0201]  312.41 537.94 0 top
UNK4CD1  0.1U-10-X7R-S2-MU  [C0201]  388.18 537.94 0 top
UNK4CD2  0.1U-10-X7R-S2-MU  [C0201]  135.24 556.2 0 top
UNK4CD3  0.1U-10-X7R-S2-MU  [C0201]  138.85 556.2 0 top
UNK4CD4  0.1U-10-X7R-S2-MU  [C0201]  400.81 537.94 0 top
UNK4CD5  0.1U-10-X7R-S2-MU  [C0201]  402.21 537.94 0 top
UNK4CD6  0.1U-10-X7R-S2-MU  [C0201]  403.61 537.94 0 top
UNK4CD7  0.1U-10-X7R-S2-MU  [C0201]  405.01 537.94 0 top
UNK4CD8  0.1U-10-X7R-S2-MU  [C0201]  406.42 537.94 0 top
UNK4CD9  0.1U-10-X7R-S2-MU  [C0201]  407.82 537.94 0 top
UNK4CD10  0.1U-10-X7R-S2-MU  [C0201]  389.58 537.94 0 top
UNK4CD11  0.1U-10-X7R-S2-MU  [C0201]  390.98 537.94 0 top
UNK4CD12  0.1U-10-X7R-S2-MU  [C0201]  392.39 537.94 0 top
UNK4CD13  0.1U-10-X7R-S2-MU  [C0201]  393.79 537.94 0 top
UNK4CD14  0.1U-10-X7R-S2-MU  [C0201]  395.19 537.94 0 top
UNK4CD15  0.1U-10-X7R-S2-MU  [C0201]  44.33 556.2 0 top
UNK4GND1  TP01  [TP_040_T]  426.7 559.38 0 top
UNK4K9  UA2-5NJ-A-V3  [RL_NECUA2_5V_V3]  253.51 524.93 0 top
UNK4K10  UA2-5NJ-A-V3  [RL_NECUA2_5V_V3]  320.13 524.93 0 top
UNK4K14  UA2-5NJ-A-V3  [RL_NECUA2_5V_V3]  309.02 524.93 0 top
UNK4K15  UA2-5NJ-A-V3  [RL_NECUA2_5V_V3]  297.92 524.93 0 top
UNK4K28  UA2-5NJ-A-V3  [RL_NECUA2_5V_V3]  286.82 524.93 0 top
UNK4K48  UA2-5NJ-A-V3  [RL_NECUA2_5V_V3]  275.71 524.93 0 top
UNK4K50  UA2-5NJ-A-V3  [RL_NECUA2_5V_V3]  264.61 524.93 0 top
UNK4K54  G6K-2F-RF-T-5V-SPECIAL  [RL_G6K2FRT_8P_5V_GR]  383.26 512.22 0 top
UNK4K55  EC2-5NJ-A  [RL_NECEC2_10P_5V]  36.71 525.68 0 top
UNK4K56  EC2-5NJ-A  [RL_NECEC2_10P_5V]  21.5 525.68 0 top
UNK4K57  EC2-5NJ-A  [RL_NECEC2_10P_5V]  6.3 525.68 0 top
UNK4K58  EC2-5NJ-A  [RL_NECEC2_10P_5V]  621.57 510.07 0 top
UNK4K59  EC2-5NJ-A  [RL_NECEC2_10P_5V]  606.37 510.07 0 top
UNK4K60  G6K-2F-RF-T-5V-SPECIAL  [RL_G6K2FRT_8P_5V_GR]  460.08 512.22 0 top
UNK4K61  G6K-2F-RF-T-5V-SPECIAL  [RL_G6K2FRT_8P_5V_GR]  485.69 512.22 0 top
UNK4K62  G6K-2F-RF-T-5V-SPECIAL  [RL_G6K2FRT_8P_5V_GR]  396.07 512.22 0 top
UNK4R11  49.9-1-S4  [R0402]  210.35 556.34 0 top
UNK4R12  49.9-1-S4  [R0402]  212.55 556.34 0 top
UNK4R13  49.9-1-S4  [R0402]  214.76 556.34 0 top
UNK4R14  49.9-1-S4  [R0402]  216.96 556.34 0 top
UNK4R15  49.9-1-S4  [R0402]  219.16 556.34 0 top
UNK4R16  49.9-1-S4  [R0402]  221.37 556.34 0 top
UNK4R17  49.9-1-S4  [R0402]  125.62 559.05 0 top
UNK4R18  49.9-1-S4  [R0402]  225.77 556.34 0 top
UNK4R19  49.9-1-S4  [R0402]  227.98 556.34 0 top
UNK4R20  49.9-1-S4  [R0402]  230.18 556.34 0 top
UNK4R21  49.9-1-S4  [R0402]  232.38 556.34 0 top
UNK4R22  49.9-1-S4  [R0402]  234.59 556.34 0 top
UNK4R23  49.9-1-S4  [R0402]  236.79 556.34 0 top
UNK4R24  49.9-1-S4  [R0402]  238.99 556.34 0 top
UNK4R25  49.9-1-S4  [R0402]  241.2 556.34 0 top
UNK4R26  49.9-1-S4  [R0402]  243.4 556.34 0 top
UNK4R51  NC/1M-1-S4  [R0402]  448.3 556.34 0 top
UNK4R52  NC/1M-1-S4  [R0402]  450.5 556.34 0 top
UNK4R53  NC/100K-1-S4  [R0402]  465.92 556.34 0 top
UNK4R54  NC/100K-1-S4  [R0402]  468.12 556.34 0 top
UNK4R55  100K-1-S4  [R0402]  479.14 556.34 0 top
UNK4R69  NC/4.7K-1-S4  [R0402]  505.58 556.34 0 top
UNK4R70  NC/4.7K-1-S4  [R0402]  507.78 556.34 0 top
UNK4R71  NC/4.7K-1-S4  [R0402]  509.99 556.34 0 top
UNK4R72  4.7K-1-S4-WA  [R0402]  415.25 556.34 0 top
UNK4R73  NC/4.7K-1-S4  [R0402]  512.19 556.34 0 top
UNK4R74  NC/4.7K-1-S4  [R0402]  514.39 556.34 0 top
UNK4R147  1.1K-1-S4  [R0402]  289.67 556.34 0 top
UNK4R148  1.1K-1-S4  [R0402]  291.87 556.34 0 top
UNK4R161  0-5-S4  [R0402]  351.36 556.34 0 top
UNK4R162  0-5-S4  [R0402]  353.56 556.34 0 top
UNK4R163  4.7K-1-S4-WA  [R0402]  413.04 556.34 0 top
UNK4R184  50-0.1-S4-HF-VI  [R0402]  430.67 556.34 0 top
UNK4R185  50-0.1-S4-HF-VI  [R0402]  432.87 556.34 0 top
UNK4R200  0-5-S4  [R0402]  355.76 556.34 0 top
UNK4R201  0-5-S4  [R0402]  357.96 556.34 0 top
UNK4R202  0-5-S4  [R0402]  360.17 556.34 0 top
UNK4R203  0-5-S4  [R0402]  362.37 556.34 0 top
UNK4R204  0-5-S4  [R0402]  364.57 556.34 0 top
UNK4R205  0-5-S4  [R0402]  366.78 556.34 0 top
UNK4R206  0-5-S4  [R0402]  368.98 556.34 0 top
UNK4R207  0-5-S4  [R0402]  371.18 556.34 0 top
UNK4R208  0-5-S4  [R0402]  373.39 556.34 0 top
UNK4R209  0-5-S4  [R0402]  375.59 556.34 0 top
UNK4SH1  SHORT  [DEFAULT_SHORT_SMALL]  615.74 556.43 0 top
UNK4SH2  SHORT  [DEFAULT_SHORT_SMALL]  3.87 559.13 0 top
UNK4SH3  SHORT  [DEFAULT_SHORT_SMALL]  8.28 559.13 0 top
UNK4SH4  SHORT  [DEFAULT_SHORT_SMALL]  10.48 559.13 0 top
UNK4SH5  SHORT  [DEFAULT_SHORT_SMALL]  12.68 559.13 0 top
UNK4SH6  SHORT  [DEFAULT_SHORT_SMALL]  14.88 559.13 0 top
UNK4SH7  SHORT  [DEFAULT_SHORT_SMALL]  17.09 559.13 0 top
UNK4SH8  SHORT  [DEFAULT_SHORT_SMALL]  19.29 559.13 0 top
UNK4SH9  SHORT  [DEFAULT_SHORT_SMALL]  21.49 559.13 0 top
UNK4SH10  SHORT  [DEFAULT_SHORT_SMALL]  617.94 556.43 0 top
UNK4SH11  SHORT  [DEFAULT_SHORT_SMALL]  620.15 556.43 0 top
UNK4SH12  SHORT  [DEFAULT_SHORT_SMALL]  622.35 556.43 0 top
UNK4SH13  SHORT  [DEFAULT_SHORT_SMALL]  624.55 556.43 0 top
UNK4SH14  SHORT  [DEFAULT_SHORT_SMALL]  626.75 556.43 0 top
UNK4SH15  SHORT  [DEFAULT_SHORT_SMALL]  628.96 556.43 0 top
UNK4SH16  SHORT  [DEFAULT_SHORT_SMALL]  631.16 556.43 0 top
UNK4SH17  SHORT  [DEFAULT_SHORT_SMALL]  -2.74 559.13 0 top
UNK4SH18  SHORT  [DEFAULT_SHORT_SMALL]  -0.54 559.13 0 top
UNK4SH19  SHORT  [DEFAULT_SHORT_SMALL]  1.67 559.13 0 top
UNK4SH20  SHORT  [DEFAULT_SHORT_SMALL]  6.07 559.13 0 top
UNK4SW1  SW-SLIDE-1-D2.54-ECE  [SW_DIPX1_2P_H5MM]  108.61 563.75 0 top
UNK4TP_VDD09_CORE  TP01  [TP_040_T]  376.21 559.38 0 top
UNK4TP_VDD_IOB_18_BOOST  TP01  [TP_040_T]  382.76 559.38 0 top
UNK4TP_VDD_IOB_18_POR  TP01  [TP_040_T]  366.3 559.38 0 top
UNK4TP_VDD_PLL_09  TP01  [TP_040_T]  364.32 559.38 0 top
UNK4TP_VDD_TX_09  TP01  [TP_040_T]  360.36 559.38 0 top
UNK4TP_VDD_TX_09_HDO  TP01  [TP_040_T]  358.38 559.38 0 top
UNK4TP_VDD_TXPST_09  TP01  [TP_040_T]  362.34 559.38 0 top
UNK4TP_VDDIO_18  TP01  [TP_040_T]  374.23 559.38 0 top
UNK4TP_VDDRX_09  TP01  [TP_040_T]  372.25 559.38 0 top
UNK4TP_VDDRX_AUX  TP01  [TP_040_T]  370.26 559.38 0 top
UNK4U5  SK-SO8-1.27-LOTES-150  [SK_SO8_150_1P27MM_LOTES]  525.65 514.02 0 top
UNK4UF1  MX25U4035FM1I-SOP8  [SOCKET_CODE]  381.45 558.9 0 top
UNK038HX-887904K4Q-A100  REF-CODE-PCB  [PCB_CODE]  23.42 581.75 0 top
UNK980HX-887904-KAG-  REF-CODE-PCB  [PCB_CODE]  22.81 581.75 0 top
UNK261103AA031  REF-CODE-SOCKET  [SOCKET_CODE]  22.2 581.75 0 top
UT_UP5V  TP03-D  [TP_060_040]  25.11 582.61 0 top
UTL1  V93K_UTL  [PG_VG93K_F_G3UTI1]  180.21 16.51 0 top
UTL2  V93K_UTL  [PG_VG93K_F_G1UTI2]  327.53 16.51 0 top
UTL3  V93K_UTL  [PG_VG93K_F_G2UTI3]  401.19 412.75 0 top
UTL4  V93K_UTL  [PG_VG93K_F_G8UTI4]  253.87 412.75 0 top
UTL5  V93K_UTL  [PG_VG93K_F_G4UTI5]  32.89 16.51 0 top
UTL6  V93K_UTL  [PG_VG93K_F_G5UTI6]  474.85 16.51 0 top
UTL7  V93K_UTL  [PG_VG93K_F_G6UTI7]  548.51 412.75 0 top
UTL8  V93K_UTL  [PG_VG93K_F_G7UTI8]  106.55 412.75 0 top
WFBGA-10X3.5X0.636-P0.65  REF-CODE-CHIP  [CHIP_CODE]  460.7 558.9 0 top

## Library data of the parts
BD29-BD44 = BD120-3A-S8: User Part Number: PNXXXXXXXXXX; Tolerance: TOL
C1 C53-C55 CB1 CB3 CB5 CB7 CB19 UNK2C1 UNK2C53-UNK2C55 UNK3C1 UNK3C53-UNK3C55 UNK4C1 UNK4C53-UNK4C55 = 0.1U-16-X-S4-MU: User Part Number: PNXXXXXXXXXX; Tolerance: TOL
C67 C71 C73 C75 C77 C79 C81 C83 C85 C87 UNK2C67 UNK2C71 UNK2C73 UNK2C75 UNK2C77 UNK2C79 UNK2C81 UNK2C83 UNK2C85 UNK2C87 UNK3C67 UNK3C71 UNK3C73 UNK3C75 UNK3C77 UNK3C79 UNK3C81 UNK3C83 UNK3C85 UNK3C87 UNK4C67 UNK4C71 UNK4C73 UNK4C75 UNK4C77 UNK4C79 UNK4C81 UNK4C83 UNK4C85 UNK4C87 = 1U-10-X-S4-MU: User Part Number: PNXXXXXXXXXX; Tolerance: TOL
C69 C70 C89-C96 CB2 CB4 CB6 CB8 CB10 CB12 CB14 CB16 UNK2C69 UNK2C70 UNK2C89-UNK2C96 UNK3C69 UNK3C70 UNK3C89-UNK3C96 UNK4C69 UNK4C70 UNK4C89-UNK4C96 = 10U-25-X7R-SA: User Part Number: PNXXXXXXXXXX; Tolerance: TOL
CA1-CA10 CA12-CA14 UNK2CA1-UNK2CA10 UNK3CA1-UNK3CA10 UNK4CA1-UNK4CA10 = 2.2U-10-X-S4-MU: User Part Number: PNXXXXXXXXXX; Tolerance: TOL
CB9 CB11 CB13 CB15 = 0.1U-25-X-S6: User Part Number: PNXXXXXXXXXX; Tolerance: TOL
CC1-CC15 UNK2CC1-UNK2CC15 UNK3CC1-UNK3CC15 UNK4CC1-UNK4CC15 = 0.47U-10-X6S-S2-TY: User Part Number: PNXXXXXXXXXX; Tolerance: TOL
CD1-CD15 UNK2CD1-UNK2CD15 UNK3CD1-UNK3CD15 UNK4CD1-UNK4CD15 = 0.1U-10-X7R-S2-MU: User Part Number: PNXXXXXXXXXX; Tolerance: TOL
CSDPS225 CSDPS229 CSDPS425 CSDPS429 = V93K_CSDPS_DPS32: User Part Number: PNXXXXXXXXXX; Tolerance: TOL
D101/D501 D102/D502 D103/D503 D105/D505 D106/D506 D107/D507 D117/D517 D118/D518 D119/D519 D121/D521 D122/D522 D123/D523 = V93K_PS1600_HD: User Part Number: PNXXXXXXXXXX; Tolerance: TOL
D104 D108-D116 D120 D124-D132 D201-D224 D231 D301 D302 D305 D306 D317 D318 D321 D322 D431 = V93K_CH: Tolerance: TOL; User Part Number: PNXXXXXXXXXX
DPS1-DPS5 DPS8 = V93K_DPS: Tolerance: TOL; User Part Number: PNXXXXXXXXXX
FD1-FD16 = FD_040_V2: Tolerance: TOL; User Part Number: PNXXXXXXXXXX
GND1 TP_S1_V25 TP_VDD09_CORE TP_VDD_EFUSE_POWER TP_VDD_EFUSE_POWER1 TP_VDD_IOB_18_BOOST TP_VDD_IOB_18_POR TP_VDD_PLL_09 TP_VDD_TX_09 TP_VDD_TX_09_HDO TP_VDD_TXPST_09 TP_VDDIO_18 TP_VDDRX_09 TP_VDDRX_AUX UNK2GND1 UNK2TP_VDD09_CORE UNK2TP_VDD_IOB_18_BOOST UNK2TP_VDD_IOB_18_POR UNK2TP_VDD_PLL_09 UNK2TP_VDD_TX_09 UNK2TP_VDD_TX_09_HDO UNK2TP_VDD_TXPST_09 UNK2TP_VDDIO_18 UNK2TP_VDDRX_09 UNK2TP_VDDRX_AUX UNK3GND1 UNK3TP_VDD09_CORE UNK3TP_VDD_IOB_18_BOOST UNK3TP_VDD_IOB_18_POR UNK3TP_VDD_PLL_09 UNK3TP_VDD_TX_09 UNK3TP_VDD_TX_09_HDO UNK3TP_VDD_TXPST_09 UNK3TP_VDDIO_18 UNK3TP_VDDRX_09 UNK3TP_VDDRX_AUX UNK4GND1 UNK4TP_VDD09_CORE UNK4TP_VDD_IOB_18_BOOST UNK4TP_VDD_IOB_18_POR UNK4TP_VDD_PLL_09 UNK4TP_VDD_TX_09 UNK4TP_VDD_TX_09_HDO UNK4TP_VDD_TXPST_09 UNK4TP_VDDIO_18 UNK4TP_VDDRX_09 UNK4TP_VDDRX_AUX = TP01: Tolerance: TOL; User Part Number: PNXXXXXXXXXX
HX8879-F04 WFBGA-10X3.5X0.636-P0.65 = REF-CODE-CHIP
K9 K10 K14 K15 K28 K48 K50 UNK2K9 UNK2K10 UNK2K14 UNK2K15 UNK2K28 UNK2K48 UNK2K50 UNK3K9 UNK3K10 UNK3K14 UNK3K15 UNK3K28 UNK3K48 UNK3K50 UNK4K9 UNK4K10 UNK4K14 UNK4K15 UNK4K28 UNK4K48 UNK4K50 = UA2-5NJ-A-V3: Tolerance: TOL; User Part Number: PNXXXXXXXXXX
K54 K60-K62 UNK2K54 UNK2K60-UNK2K62 UNK3K54 UNK3K60-UNK3K62 UNK4K54 UNK4K60-UNK4K62 = G6K-2F-RF-T-5V-SPECIAL: Tolerance: TOL; User Part Number: PNXXXXXXXXXX
K55-K59 UNK2K55-UNK2K59 UNK3K55-UNK3K59 UNK4K55-UNK4K59 = EC2-5NJ-A: Tolerance: TOL; User Part Number: PNXXXXXXXXXX
LDB1 = LDB-2-S8: User Part Number: PNXXXXXXXXXX; Tolerance: TOL
LOGO1 = LOGO_KT_KSMT
LOGO2 = LOGO_HX_Himax
LRB1 = 330-1-S6: User Part Number: PNXXXXXXXXXX; Tolerance: TOL
R11-R26 UNK2R11-UNK2R26 UNK3R11-UNK3R26 UNK4R11-UNK4R26 = 49.9-1-S4: User Part Number: PNXXXXXXXXXX; Tolerance: TOL
R51 R52 UNK2R51 UNK2R52 UNK3R51 UNK3R52 UNK4R51 UNK4R52 = 1M-1-S4: User Part Number: PNXXXXXXXXXX; Tolerance: TOL
R53-R55 UNK2R53-UNK2R55 UNK3R53-UNK3R55 UNK4R53-UNK4R55 = 100K-1-S4: User Part Number: PNXXXXXXXXXX; Tolerance: TOL
R69-R74 R163 UNK2R69-UNK2R74 UNK2R163 UNK3R69-UNK3R74 UNK3R163 UNK4R69-UNK4R74 UNK4R163 = 4.7K-1-S4-WA: User Part Number: PNXXXXXXXXXX; Tolerance: TOL
R147 R148 UNK2R147 UNK2R148 UNK3R147 UNK3R148 UNK4R147 UNK4R148 = 1.1K-1-S4: User Part Number: PNXXXXXXXXXX; Tolerance: TOL
R161 R162 R200-R209 UNK2R161 UNK2R162 UNK2R200-UNK2R209 UNK3R161 UNK3R162 UNK3R200-UNK3R209 UNK4R161 UNK4R162 UNK4R200-UNK4R209 = 0-5-S4: User Part Number: PNXXXXXXXXXX; Tolerance: TOL
R184 R185 UNK2R184 UNK2R185 UNK3R184 UNK3R185 UNK4R184 UNK4R185 = 50-0.1-S4-HF-VI: User Part Number: PNXXXXXXXXXX; Tolerance: TOL
RB1 RB2 = 10K-1-S6: User Part Number: PNXXXXXXXXXX; Tolerance: TOL
SB1-SB3 SB8 SB11 SB12 SH1-SH26 UNK2SH1-UNK2SH20 UNK3SH1-UNK3SH20 UNK4SH1-UNK4SH20 = SHORT: User Part Number: PNXXXXXXXXXX; Tolerance: TOL
SCREW1 = V93KMFHOLE: Tolerance: TOL; User Part Number: PNXXXXXXXXXX
SITE1-SITE4 = CU/887904-WFBGA75-10X3.5X0.636: Tolerance: TOL; User Part Number: PNXXXXXXXXXX
SKB1 = SKB-HIMAX-2SITE-M5-140X140-HON: Tolerance: TOL; User Part Number: PNXXXXXXXXXX
SW1 UNK2SW1 UNK3SW1 UNK4SW1 = SW-SLIDE-1-D2.54-ECE: Tolerance: TOL; User Part Number: PNXXXXXXXXXX
TPL1-TPL16 = TPL01: Tolerance: TOL; User Part Number: PNXXXXXXXXXX
U5 UNK2U5 UNK3U5 UNK4U5 = MX25V4006EM1I-13G-SO8: User Part Number: PNXXXXXXXXXX; Tolerance: TOL
UB1 = AT24C04C-SSHM-SO8: User Part Number: PNXXXXXXXXXX; Tolerance: TOL
UF1 UNK2UF1 UNK3UF1 UNK4UF1 = REF-CODE-FLASH
UNK038HX-887904K4Q-A100 UNK980HX-887904-KAG- = REF-CODE-PCB
UNK261103AA031 = REF-CODE-SOCKET
UT_UP5V = TP03-D: Tolerance: TOL; User Part Number: PNXXXXXXXXXX
UTL1-UTL8 = V93K_UTL: User Part Number: PNXXXXXXXXXX; Tolerance: TOL

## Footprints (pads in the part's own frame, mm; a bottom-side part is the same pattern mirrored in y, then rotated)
C0201
  rect 0.305x0.356 smd: 1(-0.3,0) 2(0.3,0)
C0402
  custom 0.15x0.15 smd: 1(-0.5,0) 2(0.5,0)
C0603
  rect 0.889x0.889 smd: 1(-0.85,0) 2(0.85,0)
C1206
  rect 1.321x1.829 smd: 1(-1.25,0) 2(1.25,0)
CHIP_CODE
  round 0.051 smd: 1(0,0)
DEFAULT_SHORT_SMALL
  custom 0.07x0.07 smd: 1(-0.5,0) 2(0.5,0)
FB0805
  rect 1.118x1.372 smd: 1(-0.965,0) 2(0.965,0)
FD_040_V2
  round 1.016 smd: 1(0,0)
LED_0805
  rect 1.118x1.372 smd: 1(0.95,0) 2(-0.95,0)
LOGO_HX_HIMAX
  round 0.051 smd: 1(0.831,1.487)
LOGO_KT_KSMT
  round 0.051 smd: 1(-0.711,-0.711)
PCB_CODE
  round 0.051 smd: 1(0,0)
PG_VG93K_F_FULLOUTLINE
  round 0.508 hole 3.2 unplated: (-287.604,198.12) (-287.604,102.006) (-287.604,0) (-287.604,-102.006) (-287.604,-198.12) (-220.98,157.48) (-220.98,-157.48) (-140.276,198.12) (-140.276,102.006) (-140.276,0) (-140.276,-102.006) (-140.276,-198.12) (-73.66,157.48) (-73.66,-157.48) (7.044,198.12) (7.044,102.006) (7.044,-102.006) (7.044,-198.12) (73.66,157.48) (73.66,-157.48) (140.304,198.12) (140.304,102.006) (140.304,0) (140.304,-102.006) (140.304,-198.12) (220.98,157.48) (220.98,-157.48) (287.604,198.12) (287.604,102.006) (287.604,0) (287.604,-102.006) (287.604,-198.12)
  round 0.508 hole 6 unplated: (-70,70) (-70,-70) (70,70) (70,-70)
PG_VG93K_F_G1D104
  round 1.778 hole 0.711: 01(-20.32,-1.27) 02(-17.78,1.27) 03(-15.24,-1.27) 04(-12.7,1.27) 05(-10.16,-1.27) 06(-7.62,1.27) 07(-5.08,-1.27) 08(-2.54,1.27) 09(0,-1.27) 10(2.54,1.27) 11(5.08,-1.27) 12(7.62,1.27) 13(10.16,-1.27) 14(12.7,1.27) 15(15.24,-1.27) 16(17.78,1.27) 17(20.32,-1.27)
  rect 1.778x1.778 hole 0.711: A1(-20.32,-3.81) A2(-17.78,-1.27) A3(-15.24,-3.81) A4(-12.7,-1.27) A5(-10.16,-3.81) A6(-7.62,-1.27) A7(-5.08,-3.81) A8(-2.54,-1.27) A9(0,-3.81) A10(2.54,-1.27) A11(5.08,-3.81) A12(7.62,-1.27) A13(10.16,-3.81) A14(12.7,-1.27) A15(15.24,-3.81) A16(17.78,-1.27) A17(20.32,-3.81) B1(-20.32,1.27) B2(-17.78,3.81) B3(-15.24,1.27) B4(-12.7,3.81) B5(-10.16,1.27) B6(-7.62,3.81) B7(-5.08,1.27) B8(-2.54,3.81) B9(0,1.27) B10(2.54,3.81) B11(5.08,1.27) B12(7.62,3.81) B13(10.16,1.27) B14(12.7,3.81) B15(15.24,1.27) B16(17.78,3.81) B17(20.32,1.27)
PG_VG93K_F_G1D108
  round 1.778 hole 0.711: 01(-20.32,-1.27) 02(-17.78,1.27) 03(-15.24,-1.27) 04(-12.7,1.27) 05(-10.16,-1.27) 06(-7.62,1.27) 07(-5.08,-1.27) 08(-2.54,1.27) 09(0,-1.27) 10(2.54,1.27) 11(5.08,-1.27) 12(7.62,1.27) 13(10.16,-1.27) 14(12.7,1.27) 15(15.24,-1.27) 16(17.78,1.27) 17(20.32,-1.27)
  rect 1.778x1.778 hole 0.711: A1(-20.32,-3.81) A2(-17.78,-1.27) A3(-15.24,-3.81) A4(-12.7,-1.27) A5(-10.16,-3.81) A6(-7.62,-1.27) A7(-5.08,-3.81) A8(-2.54,-1.27) A9(0,-3.81) A10(2.54,-1.27) A11(5.08,-3.81) A12(7.62,-1.27) A13(10.16,-3.81) A14(12.7,-1.27) A15(15.24,-3.81) A16(17.78,-1.27) A17(20.32,-3.81) B1(-20.32,1.27) B2(-17.78,3.81) B3(-15.24,1.27) B4(-12.7,3.81) B5(-10.16,1.27) B6(-7.62,3.81) B7(-5.08,1.27) B8(-2.54,3.81) B9(0,1.27) B10(2.54,3.81) B11(5.08,1.27) B12(7.62,3.81) B13(10.16,1.27) B14(12.7,3.81) B15(15.24,1.27) B16(17.78,3.81) B17(20.32,1.27)
PG_VG93K_F_G1D301
  round 1.778 hole 0.711: 01(-20.32,-1.27) 02(-17.78,1.27) 03(-15.24,-1.27) 04(-12.7,1.27) 05(-10.16,-1.27) 06(-7.62,1.27) 07(-5.08,-1.27) 08(-2.54,1.27) 09(0,-1.27) 10(2.54,1.27) 11(5.08,-1.27) 12(7.62,1.27) 13(10.16,-1.27) 14(12.7,1.27) 15(15.24,-1.27) 16(17.78,1.27) 17(20.32,-1.27)
  rect 1.778x1.778 hole 0.711: A1(-20.32,-3.81) A2(-17.78,-1.27) A3(-15.24,-3.81) A4(-12.7,-1.27) A5(-10.16,-3.81) A6(-7.62,-1.27) A7(-5.08,-3.81) A8(-2.54,-1.27) A9(0,-3.81) A10(2.54,-1.27) A11(5.08,-3.81) A12(7.62,-1.27) A13(10.16,-3.81) A14(12.7,-1.27) A15(15.24,-3.81) A16(17.78,-1.27) A17(20.32,-3.81) B1(-20.32,1.27) B2(-17.78,3.81) B3(-15.24,1.27) B4(-12.7,3.81) B5(-10.16,1.27) B6(-7.62,3.81) B7(-5.08,1.27) B8(-2.54,3.81) B9(0,1.27) B10(2.54,3.81) B11(5.08,1.27) B12(7.62,3.81) B13(10.16,1.27) B14(12.7,3.81) B15(15.24,1.27) B16(17.78,3.81) B17(20.32,1.27)
PG_VG93K_F_G1D302
  round 1.778 hole 0.711: 01(-20.32,-1.27) 02(-17.78,1.27) 03(-15.24,-1.27) 04(-12.7,1.27) 05(-10.16,-1.27) 06(-7.62,1.27) 07(-5.08,-1.27) 08(-2.54,1.27) 09(0,-1.27) 10(2.54,1.27) 11(5.08,-1.27) 12(7.62,1.27) 13(10.16,-1.27) 14(12.7,1.27) 15(15.24,-1.27) 16(17.78,1.27) 17(20.32,-1.27)
  rect 1.778x1.778 hole 0.711: A1(-20.32,-3.81) A2(-17.78,-1.27) A3(-15.24,-3.81) A4(-12.7,-1.27) A5(-10.16,-3.81) A6(-7.62,-1.27) A7(-5.08,-3.81) A8(-2.54,-1.27) A9(0,-3.81) A10(2.54,-1.27) A11(5.08,-3.81) A12(7.62,-1.27) A13(10.16,-3.81) A14(12.7,-1.27) A15(15.24,-3.81) A16(17.78,-1.27) A17(20.32,-3.81) B1(-20.32,1.27) B2(-17.78,3.81) B3(-15.24,1.27) B4(-12.7,3.81) B5(-10.16,1.27) B6(-7.62,3.81) B7(-5.08,1.27) B8(-2.54,3.81) B9(0,1.27) B10(2.54,3.81) B11(5.08,1.27) B12(7.62,3.81) B13(10.16,1.27) B14(12.7,3.81) B15(15.24,1.27) B16(17.78,3.81) B17(20.32,1.27)
PG_VG93K_F_G1D305
  round 1.778 hole 0.711: 01(-20.32,-1.27) 02(-17.78,1.27) 03(-15.24,-1.27) 04(-12.7,1.27) 05(-10.16,-1.27) 06(-7.62,1.27) 07(-5.08,-1.27) 08(-2.54,1.27) 09(0,-1.27) 10(2.54,1.27) 11(5.08,-1.27) 12(7.62,1.27) 13(10.16,-1.27) 14(12.7,1.27) 15(15.24,-1.27) 16(17.78,1.27) 17(20.32,-1.27)
  rect 1.778x1.778 hole 0.711: A1(-20.32,-3.81) A2(-17.78,-1.27) A3(-15.24,-3.81) A4(-12.7,-1.27) A5(-10.16,-3.81) A6(-7.62,-1.27) A7(-5.08,-3.81) A8(-2.54,-1.27) A9(0,-3.81) A10(2.54,-1.27) A11(5.08,-3.81) A12(7.62,-1.27) A13(10.16,-3.81) A14(12.7,-1.27) A15(15.24,-3.81) A16(17.78,-1.27) A17(20.32,-3.81) B1(-20.32,1.27) B2(-17.78,3.81) B3(-15.24,1.27) B4(-12.7,3.81) B5(-10.16,1.27) B6(-7.62,3.81) B7(-5.08,1.27) B8(-2.54,3.81) B9(0,1.27) B10(2.54,3.81) B11(5.08,1.27) B12(7.62,3.81) B13(10.16,1.27) B14(12.7,3.81) B15(15.24,1.27) B16(17.78,3.81) B17(20.32,1.27)
PG_VG93K_F_G1D306
  round 1.778 hole 0.711: 01(-20.32,-1.27) 02(-17.78,1.27) 03(-15.24,-1.27) 04(-12.7,1.27) 05(-10.16,-1.27) 06(-7.62,1.27) 07(-5.08,-1.27) 08(-2.54,1.27) 09(0,-1.27) 10(2.54,1.27) 11(5.08,-1.27) 12(7.62,1.27) 13(10.16,-1.27) 14(12.7,1.27) 15(15.24,-1.27) 16(17.78,1.27) 17(20.32,-1.27)
  rect 1.778x1.778 hole 0.711: A1(-20.32,-3.81) A2(-17.78,-1.27) A3(-15.24,-3.81) A4(-12.7,-1.27) A5(-10.16,-3.81) A6(-7.62,-1.27) A7(-5.08,-3.81) A8(-2.54,-1.27) A9(0,-3.81) A10(2.54,-1.27) A11(5.08,-3.81) A12(7.62,-1.27) A13(10.16,-3.81) A14(12.7,-1.27) A15(15.24,-3.81) A16(17.78,-1.27) A17(20.32,-3.81) B1(-20.32,1.27) B2(-17.78,3.81) B3(-15.24,1.27) B4(-12.7,3.81) B5(-10.16,1.27) B6(-7.62,3.81) B7(-5.08,1.27) B8(-2.54,3.81) B9(0,1.27) B10(2.54,3.81) B11(5.08,1.27) B12(7.62,3.81) B13(10.16,1.27) B14(12.7,3.81) B15(15.24,1.27) B16(17.78,3.81) B17(20.32,1.27)
PG_VG93K_F_G1DPS1
  round 1.778 hole 0.711: A01(-20.32,-2.54) A02(-17.78,-2.54) A03(-15.24,-2.54) A04(-12.7,-2.54) A05(-10.16,-2.54) A06(-7.62,-2.54) A07(-5.08,-2.54) A08(-2.54,-2.54) A09(0,-2.54) A10(2.54,-2.54) A11(5.08,-2.54) A12(7.62,-2.54) A13(10.16,-2.54) A14(12.7,-2.54) A15(15.24,-2.54) A16(17.78,-2.54) A17(20.32,-2.54) B01(-20.32,0) B02(-17.78,0) B03(-15.24,0) B04(-12.7,0) B05(-10.16,0) B06(-7.62,0) B07(-5.08,0) B08(-2.54,0) B09(0,0) B10(2.54,0) B11(5.08,0) B12(7.62,0) B13(10.16,0) B14(12.7,0) B15(15.24,0) B16(17.78,0) B17(20.32,0) C01(-20.32,2.54) C02(-17.78,2.54) C03(-15.24,2.54) C04(-12.7,2.54) C05(-10.16,2.54) C06(-7.62,2.54) C07(-5.08,2.54) C08(-2.54,2.54) C09(0,2.54) C10(2.54,2.54) C11(5.08,2.54) C12(7.62,2.54) C13(10.16,2.54) C14(12.7,2.54) C15(15.24,2.54) C16(17.78,2.54) C17(20.32,2.54)
PG_VG93K_F_G1UTI2
  round 1.778 hole 0.711: A01(-20.32,-1.27) A02(-17.78,-1.27) A03(-15.24,-1.27) A04(-12.7,-1.27) A05(-10.16,-1.27) A06(-7.62,-1.27) A07(-5.08,-1.27) A08(-2.54,-1.27) A09(0,-1.27) A10(2.54,-1.27) A11(5.08,-1.27) A12(7.62,-1.27) A13(10.16,-1.27) A14(12.7,-1.27) A15(15.24,-1.27) A16(17.78,-1.27) A17(20.32,-1.27) B01(-20.32,1.27) B02(-17.78,1.27) B03(-15.24,1.27) B04(-12.7,1.27) B05(-10.16,1.27) B06(-7.62,1.27) B07(-5.08,1.27) B08(-2.54,1.27) B09(0,1.27) B10(2.54,1.27) B11(5.08,1.27) B12(7.62,1.27) B13(10.16,1.27) B14(12.7,1.27) B15(15.24,1.27) B16(17.78,1.27) B17(20.32,1.27)
PG_VG93K_F_G2D109
  round 1.778 hole 0.711: 01(20.32,1.27) 02(17.78,-1.27) 03(15.24,1.27) 04(12.7,-1.27) 05(10.16,1.27) 06(7.62,-1.27) 07(5.08,1.27) 08(2.54,-1.27) 09(0,1.27) 10(-2.54,-1.27) 11(-5.08,1.27) 12(-7.62,-1.27) 13(-10.16,1.27) 14(-12.7,-1.27) 15(-15.24,1.27) 16(-17.78,-1.27) 17(-20.32,1.27)
  rect 1.778x1.778 hole 0.711: A1(20.32,3.81) A2(17.78,1.27) A3(15.24,3.81) A4(12.7,1.27) A5(10.16,3.81) A6(7.62,1.27) A7(5.08,3.81) A8(2.54,1.27) A9(0,3.81) A10(-2.54,1.27) A11(-5.08,3.81) A12(-7.62,1.27) A13(-10.16,3.81) A14(-12.7,1.27) A15(-15.24,3.81) A16(-17.78,1.27) A17(-20.32,3.81) B1(20.32,-1.27) B2(17.78,-3.81) B3(15.24,-1.27) B4(12.7,-3.81) B5(10.16,-1.27) B6(7.62,-3.81) B7(5.08,-1.27) B8(2.54,-3.81) B9(0,-1.27) B10(-2.54,-3.81) B11(-5.08,-1.27) B12(-7.62,-3.81) B13(-10.16,-1.27) B14(-12.7,-3.81) B15(-15.24,-1.27) B16(-17.78,-3.81) B17(-20.32,-1.27)
PG_VG93K_F_G2D110
  round 1.778 hole 0.711: 01(20.32,1.27) 02(17.78,-1.27) 03(15.24,1.27) 04(12.7,-1.27) 05(10.16,1.27) 06(7.62,-1.27) 07(5.08,1.27) 08(2.54,-1.27) 09(0,1.27) 10(-2.54,-1.27) 11(-5.08,1.27) 12(-7.62,-1.27) 13(-10.16,1.27) 14(-12.7,-1.27) 15(-15.24,1.27) 16(-17.78,-1.27) 17(-20.32,1.27)
  rect 1.778x1.778 hole 0.711: A1(20.32,3.81) A2(17.78,1.27) A3(15.24,3.81) A4(12.7,1.27) A5(10.16,3.81) A6(7.62,1.27) A7(5.08,3.81) A8(2.54,1.27) A9(0,3.81) A10(-2.54,1.27) A11(-5.08,3.81) A12(-7.62,1.27) A13(-10.16,3.81) A14(-12.7,1.27) A15(-15.24,3.81) A16(-17.78,1.27) A17(-20.32,3.81) B1(20.32,-1.27) B2(17.78,-3.81) B3(15.24,-1.27) B4(12.7,-3.81) B5(10.16,-1.27) B6(7.62,-3.81) B7(5.08,-1.27) B8(2.54,-3.81) B9(0,-1.27) B10(-2.54,-3.81) B11(-5.08,-1.27) B12(-7.62,-3.81) B13(-10.16,-1.27) B14(-12.7,-3.81) B15(-15.24,-1.27) B16(-17.78,-3.81) B17(-20.32,-1.27)
PG_VG93K_F_G2D111
  round 1.778 hole 0.711: 01(20.32,1.27) 02(17.78,-1.27) 03(15.24,1.27) 04(12.7,-1.27) 05(10.16,1.27) 06(7.62,-1.27) 07(5.08,1.27) 08(2.54,-1.27) 09(0,1.27) 10(-2.54,-1.27) 11(-5.08,1.27) 12(-7.62,-1.27) 13(-10.16,1.27) 14(-12.7,-1.27) 15(-15.24,1.27) 16(-17.78,-1.27) 17(-20.32,1.27)
  rect 1.778x1.778 hole 0.711: A1(20.32,3.81) A2(17.78,1.27) A3(15.24,3.81) A4(12.7,1.27) A5(10.16,3.81) A6(7.62,1.27) A7(5.08,3.81) A8(2.54,1.27) A9(0,3.81) A10(-2.54,1.27) A11(-5.08,3.81) A12(-7.62,1.27) A13(-10.16,3.81) A14(-12.7,1.27) A15(-15.24,3.81) A16(-17.78,1.27) A17(-20.32,3.81) B1(20.32,-1.27) B2(17.78,-3.81) B3(15.24,-1.27) B4(12.7,-3.81) B5(10.16,-1.27) B6(7.62,-3.81) B7(5.08,-1.27) B8(2.54,-3.81) B9(0,-1.27) B10(-2.54,-3.81) B11(-5.08,-1.27) B12(-7.62,-3.81) B13(-10.16,-1.27) B14(-12.7,-3.81) B15(-15.24,-1.27) B16(-17.78,-3.81) B17(-20.32,-1.27)
